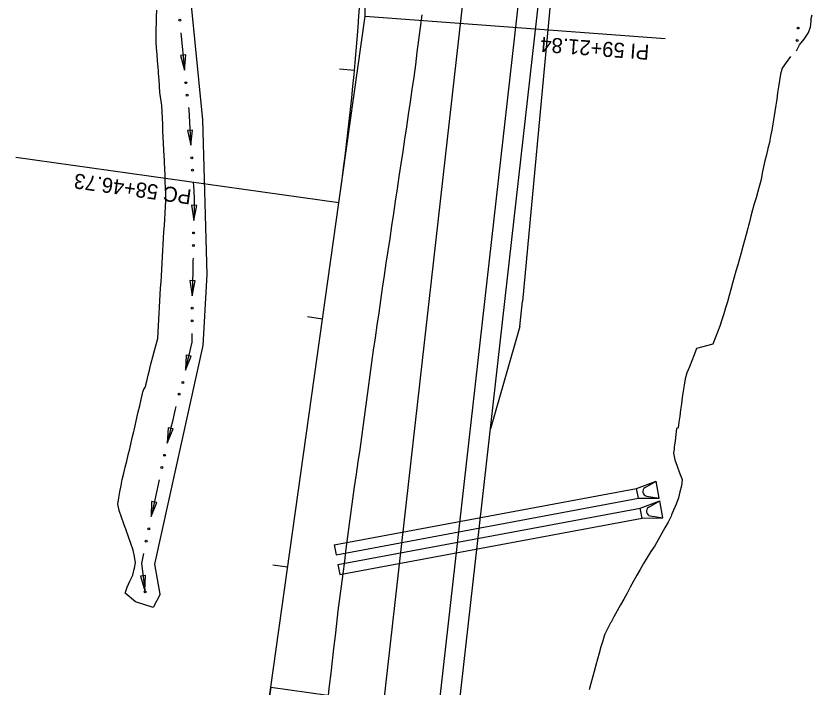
# Model space of a CAD drawing. Extents: x 1304554 to 1314558, y 2088110 to 2090513.
# Drawn here: x 1313857.1 to 1314174.4, y 2088772.7 to 2089040.4 of the extents above; entities that cross this region are included whole.
import ezdxf

# ---------------------------------------------------------------- set-up
doc = ezdxf.new("R2010")
doc.units = 0
for name, color, linetype in [('R_Drainage', 7, 'Continuous'), ('R_Horz Alg', 7, 'Continuous'), ('R_Horz Alg Annot', 7, 'Continuous'), ('R_Horz Alg Stationing', 7, 'Continuous'), ('R_Proposed Const Limits', 7, 'Continuous'), ('R_Proposed Road', 7, 'Continuous'), ('R_Shld_GR', 7, 'Continuous'), ('R_Shoulder', 7, 'Continuous'), ('R_Special Ditch', 7, 'Continuous')]:
    doc.layers.add(name, color=color, linetype=linetype)

msp = doc.modelspace()

# ---------------------------------------------------------------- linework, layer by layer
at = {"layer": 'R_Drainage'}
for p, q in [((1313924.75, 2089024.83), (1313922.64, 2089024.62)), ((1313922.64, 2089024.62), (1313924.29, 2089018.75)), ((1313924.29, 2089018.75), (1313924.75, 2089024.83)), ((1313927.5, 2088994.89), (1313925.39, 2088994.76)), ((1313925.39, 2088994.76), (1313926.8, 2088988.83)), ((1313926.8, 2088988.83), (1313927.5, 2088994.89)), ((1313929.19, 2088964.81), (1313927.07, 2088964.86)), ((1313927.07, 2088964.86), (1313927.98, 2088958.84)), ((1313927.98, 2088958.84), (1313929.19, 2088964.81)), ((1313928.54, 2088934.79), (1313926.43, 2088934.82)), ((1313926.43, 2088934.82), (1313927.38, 2088928.81)), ((1313927.38, 2088928.81), (1313928.54, 2088934.79)), ((1313924.87, 2088905.14), (1313924.61, 2088899.05)), ((1313924.61, 2088899.05), (1313926.94, 2088904.68)), ((1313926.94, 2088904.68), (1313924.87, 2088905.14)), ((1313917.72, 2088876.11), (1313917.4, 2088870.02)), ((1313917.4, 2088870.02), (1313919.78, 2088875.63)), ((1313919.78, 2088875.63), (1313917.72, 2088876.11)), ((1314104.47, 2088851.9), (1314112.23, 2088854.88)), ((1314107.82, 2088852.24), (1314112.23, 2088854.88)), ((1314113.51, 2088847.99), (1314112.23, 2088854.88)), ((1313983.92, 2088829.42), (1314104.47, 2088851.9)), ((1314105.2, 2088847.97), (1314104.47, 2088851.9)), ((1313911.17, 2088846.77), (1313910.97, 2088840.68)), ((1313913.24, 2088846.33), (1313911.17, 2088846.77)), ((1313984.65, 2088825.49), (1314105.2, 2088847.97)), ((1314105.2, 2088847.97), (1314113.51, 2088847.99)), ((1314105.94, 2088844.04), (1314113.69, 2088847.01)), ((1314108.46, 2088848.86), (1314113.51, 2088847.99)), ((1314109.29, 2088844.38), (1314113.69, 2088847.01)), ((1314114.98, 2088840.13), (1314113.69, 2088847.01)), ((1313910.97, 2088840.68), (1313913.24, 2088846.33)), ((1313985.38, 2088821.56), (1314105.94, 2088844.04)), ((1314106.67, 2088840.11), (1314105.94, 2088844.04)), ((1313986.12, 2088817.63), (1314106.67, 2088840.11)), ((1314106.67, 2088840.11), (1314114.98, 2088840.13)), ((1314109.92, 2088841), (1314114.98, 2088840.13)), ((1313983.92, 2088829.42), (1313984.65, 2088825.49)), ((1313985.38, 2088821.56), (1313986.12, 2088817.63)), ((1313908.77, 2088817.2), (1313906.67, 2088816.94)), ((1313906.67, 2088816.94), (1313908.44, 2088811.11)), ((1313908.44, 2088811.11), (1313908.77, 2088817.2))]:
    msp.add_line(p, q, dxfattribs=at)
for points in [[(1313922.82, 2089033.68), (1313924.29, 2089018.75)], [(1313925.86, 2089003.84), (1313925.86, 2089003.8)], [(1313925.86, 2089003.8), (1313925.98, 2089003.04), (1313926.12, 2089000.61), (1313926.26, 2088998.07), (1313926.41, 2088995.54), (1313926.55, 2088993.01), (1313926.7, 2088990.47), (1313926.8, 2088988.83)], [(1313927.71, 2088973.86), (1313927.71, 2088973.82)], [(1313927.71, 2088973.82), (1313927.78, 2088972.73), (1313927.94, 2088970.2), (1313928.1, 2088967.71), (1313928.14, 2088965.28), (1313928.08, 2088962.81), (1313928.02, 2088960.3), (1313927.98, 2088958.84)], [(1313927.66, 2088943.8), (1313927.63, 2088942.72), (1313927.58, 2088940.21), (1313927.54, 2088937.7), (1313927.49, 2088935.19), (1313927.45, 2088932.67), (1313927.41, 2088930.16), (1313927.38, 2088928.81)], [(1313927.66, 2088943.84), (1313927.66, 2088943.8)], [(1313927.17, 2088913.77), (1313927.15, 2088912.57), (1313927.13, 2088910.27), (1313926.61, 2088908.03), (1313926.06, 2088905.57), (1313925.51, 2088903.11), (1313924.96, 2088900.65), (1313924.61, 2088899.05)], [(1313920.84, 2088884.62), (1313920.59, 2088883.57), (1313920, 2088881.12), (1313919.41, 2088878.67), (1313918.83, 2088876.21), (1313918.26, 2088873.76), (1313918.14, 2088873.26), (1313917.69, 2088871.3), (1313917.4, 2088870.02)], [(1313920.85, 2088884.66), (1313920.84, 2088884.62)], [(1313914.12, 2088855.35), (1313913.84, 2088854.1), (1313913.31, 2088851.64), (1313912.78, 2088849.18), (1313912.25, 2088846.72), (1313911.73, 2088844.26), (1313911.21, 2088841.8), (1313910.97, 2088840.68)], [(1313914.12, 2088855.38), (1313914.12, 2088855.35)], [(1313907.94, 2088825.95), (1313907.13, 2088821.93), (1313908.39, 2088811.52)], [(1313907.95, 2088825.99), (1313907.94, 2088825.95)]]:
    msp.add_lwpolyline(points, dxfattribs=at)
for centre in [(1313922.36, 2089038.68), (1313924.81, 2089013.77), (1313925.3, 2089008.79), (1313927.13, 2088983.84), (1313927.44, 2088978.84), (1313927.9, 2088953.83), (1313927.79, 2088948.82), (1313927.34, 2088923.8), (1313927.27, 2088918.79), (1313923.6, 2088894.15), (1313922.07, 2088889.49), (1313916.33, 2088865.13), (1313915.23, 2088860.24), (1313909.98, 2088835.77), (1313908.98, 2088830.87), (1313908.55, 2088810.62), (1313908.55, 2088810.62)]:
    msp.add_circle(centre, 0.375, dxfattribs=at)
for centre in [(1314108.77, 2088850.67), (1314110.24, 2088842.81)]:
    msp.add_arc(centre, 1.83, 120.881, 260.2438, dxfattribs=at)
at = {"layer": 'R_Horz Alg'}
msp.add_line((1313958.64, 2088772.67), (1313985.8, 2088965.89), dxfattribs=at)
msp.add_line((1313958.64, 2088772.67), (1313985.8, 2088965.89), dxfattribs=at)
for centre, start, end in [((1312851.03, 2089125.37), 352, 359.5), ((1312851.03, 2089125.37), 352, 359.5), ((1315093.4, 2088613.19), 172, 187), ((1315093.4, 2088613.19), 172, 187)]:
    msp.add_arc(centre, 1145.92, start, end, dxfattribs=at)
at = {"layer": 'R_Horz Alg Annot'}
for points in [[(1313985.8, 2088965.89), (1313996.25, 2089040.27), (1313996.9, 2089115.37)], [(1313996.25, 2089040.27), (1314115.92, 2089031.38)], [(1313985.8, 2088965.89), (1313857.06, 2088983.99)], [(1313956.03, 2088473.54), (1313937.64, 2088623.28), (1313958.64, 2088772.67)], [(1313958.64, 2088772.67), (1314087.38, 2088754.58)]]:
    msp.add_lwpolyline(points, dxfattribs=at)
at = {"layer": 'R_Horz Alg Stationing'}
for points in [[(1313986.01, 2089019.36), (1313991.98, 2089018.8)], [(1313973.35, 2088920.45), (1313979.29, 2088919.62)], [(1313959.43, 2088821.43), (1313965.38, 2088820.59)]]:
    msp.add_lwpolyline(points, dxfattribs=at)
at = {"layer": 'R_Proposed Const Limits'}
for points in [[(1313914.54, 2088809.73), (1313912.39, 2088821.75), (1313931.7, 2088908.87), (1313933.34, 2088937.28), (1313931.57, 2088998.96), (1313916.24, 2089153.35)], [(1313915.23, 2089004.69), (1313914.49, 2089009.8), (1313914.29, 2089012.34), (1313914.1, 2089014.88), (1313913.91, 2089017.42), (1313913.87, 2089018.02), (1313913.84, 2089018.37), (1313913.72, 2089019.95), (1313913.53, 2089022.49), (1313913.33, 2089025.03), (1313913.12, 2089027.57), (1313912.92, 2089030.11), (1313912.95, 2089032.62), (1313913.01, 2089035.13), (1313913.08, 2089037.64), (1313913.14, 2089040.15), (1313913.18, 2089042.66)], [(1313981.46, 2088768.27), (1313982.06, 2088773.24), (1313982.66, 2088778.2), (1313983.25, 2088783.17), (1313983.85, 2088788.13), (1313984.43, 2088793.1), (1313985, 2088798.06), (1313985.57, 2088803.03), (1313986.15, 2088808), (1313986.81, 2088812.95), (1313987.46, 2088817.91), (1313988.11, 2088822.87), (1313988.75, 2088827.83), (1313989.4, 2088832.79), (1313990.04, 2088837.75), (1313990.71, 2088842.7), (1313991.38, 2088847.66), (1313992.08, 2088852.61), (1313992.8, 2088857.56), (1313993.52, 2088862.51), (1313994.24, 2088867.46), (1313994.97, 2088872.41), (1313995.66, 2088877.37), (1313996.34, 2088882.32), (1313996.98, 2088887.28), (1313997.62, 2088892.24), (1313998.27, 2088897.2), (1313998.96, 2088902.15), (1313999.66, 2088907.11), (1314000.37, 2088912.06), (1314001.08, 2088917.01), (1314001.79, 2088921.96), (1314002.5, 2088926.91), (1314003.22, 2088931.86), (1314003.95, 2088936.81), (1314004.67, 2088941.76), (1314005.43, 2088946.71), (1314006.18, 2088951.66), (1314006.91, 2088956.61), (1314007.65, 2088961.56), (1314008.38, 2088966.5), (1314009.13, 2088971.45), (1314009.87, 2088976.4), (1314010.63, 2088981.35), (1314011.39, 2088986.29), (1314012.12, 2088991.24), (1314012.84, 2088996.19), (1314013.57, 2089001.14), (1314014.3, 2089006.09), (1314015.04, 2089011.04), (1314015.77, 2089015.99), (1314016.42, 2089020.95), (1314017.06, 2089025.91), (1314017.73, 2089030.86), (1314018.38, 2089035.82), (1314019.01, 2089040.78)], [(1314168.16, 2089026.47), (1314169.41, 2089028.84), (1314171.31, 2089031.14), (1314172.82, 2089033.49), (1314173.83, 2089035.89), (1314174.04, 2089038.38), (1314174.12, 2089039.32), (1314174.42, 2089040.86)], [(1314165.83, 2089024.21), (1314164.13, 2089021.89), (1314162.45, 2089019.56), (1314161.86, 2089017.12), (1314161.45, 2089014.65), (1314161.04, 2089012.18), (1314160.65, 2089009.7), (1314160.31, 2089007.23), (1314159.96, 2089004.75), (1314159.61, 2089002.27), (1314159.2, 2088999.8), (1314158.78, 2088997.34), (1314158.35, 2088994.87), (1314157.91, 2088992.4), (1314157.63, 2088990.86), (1314157.55, 2088990.52), (1314157.41, 2088989.94), (1314156.8, 2088987.5), (1314156.2, 2088985.05), (1314155.61, 2088982.6), (1314155.03, 2088980.15), (1314154.54, 2088977.69), (1314154.07, 2088975.22), (1314153.45, 2088972.78), (1314152.76, 2088970.34), (1314152.08, 2088967.9), (1314151.39, 2088965.46), (1314150.7, 2088963.02), (1314150.06, 2088960.58), (1314149.43, 2088958.14), (1314149.08, 2088956.74), (1314148.8, 2088955.69), (1314148.14, 2088953.25), (1314147.47, 2088950.81), (1314146.8, 2088948.37), (1314146.13, 2088945.93), (1314145.45, 2088943.49), (1314144.77, 2088941.05), (1314144.09, 2088938.61), (1314143.4, 2088936.17), (1314142.72, 2088933.74), (1314142.03, 2088931.3), (1314141.34, 2088928.86), (1314140.65, 2088926.42), (1314139.95, 2088923.98), (1314139.24, 2088921.55), (1314138.47, 2088919.12), (1314137.69, 2088916.69), (1314136.78, 2088914.28), (1314135.8, 2088911.87), (1314134.82, 2088909.47), (1314128.38, 2088907.68), (1314127.42, 2088905.27), (1314126.46, 2088902.86), (1314125.5, 2088900.46), (1314124.54, 2088898.05), (1314123.87, 2088895.61), (1314123.37, 2088893.15), (1314123, 2088890.67), (1314122.66, 2088888.2), (1314122.32, 2088885.72), (1314121.98, 2088883.24), (1314121.64, 2088880.77), (1314121.29, 2088878.29), (1314120.98, 2088876.05), (1314120.39, 2088875.87), (1314120.09, 2088873.39), (1314119.79, 2088870.91), (1314119.49, 2088868.43), (1314119.39, 2088867.66), (1314119.22, 2088865.94), (1314119.67, 2088863.38), (1314120.65, 2088860.75), (1314121.63, 2088858.12), (1314122.61, 2088855.5), (1314122.36, 2088853.01), (1314121.75, 2088850.56), (1314121.18, 2088848.11), (1314120.21, 2088845.7), (1314119.23, 2088843.3), (1314118.43, 2088841.38), (1314118.23, 2088840.9), (1314117.08, 2088838.51), (1314115.71, 2088836.15), (1314114.38, 2088833.78), (1314113.05, 2088831.42), (1314111.68, 2088829.06), (1314110.19, 2088826.71), (1314108.7, 2088824.36), (1314107.21, 2088822.01), (1314105.9, 2088819.64), (1314104.59, 2088817.28), (1314103.27, 2088814.91), (1314101.96, 2088812.54), (1314100.65, 2088810.17), (1314099.35, 2088807.8), (1314098.04, 2088805.44), (1314096.73, 2088803.07), (1314095.43, 2088800.7), (1314094.29, 2088798.61), (1314094.13, 2088798.33), (1314092.83, 2088795.96), (1314091.65, 2088793.58), (1314090.95, 2088791.14), (1314090.27, 2088788.7), (1314089.6, 2088786.26), (1314088.93, 2088783.82), (1314088.26, 2088781.38), (1314087.58, 2088778.94), (1314086.89, 2088776.5), (1314086.21, 2088774.06), (1314085.54, 2088771.62)], [(1313900.65, 2088810.1), (1313901.39, 2088812.53), (1313902.53, 2088814.92), (1313903.66, 2088817.3), (1313904.25, 2088819.75), (1313904.32, 2088820.05), (1313904.79, 2088822.21), (1313904.39, 2088824.77), (1313903.85, 2088827.35), (1313902.88, 2088829.97), (1313901.95, 2088832.59), (1313901.02, 2088835.21), (1313900.09, 2088837.83), (1313899.17, 2088840.45), (1313898.25, 2088843.07), (1313897.62, 2088845.66), (1313898.06, 2088848.13), (1313898.5, 2088850.59), (1313898.95, 2088853.06), (1313899.41, 2088855.52), (1313900.02, 2088857.97), (1313900.63, 2088860.42), (1313901.24, 2088862.86), (1313901.86, 2088865.31), (1313902.47, 2088867.76), (1313903.01, 2088870.21), (1313903.57, 2088872.66), (1313904.01, 2088874.63), (1313904.13, 2088875.12), (1313904.69, 2088877.57), (1313905.26, 2088880.02), (1313905.83, 2088882.47), (1313906.41, 2088884.92), (1313906.99, 2088887.37), (1313907.58, 2088889.82), (1313907.7, 2088890.31), (1313907.99, 2088891.52), (1313908.64, 2088892.22), (1313909.18, 2088894.67), (1313909.79, 2088897.12), (1313910.41, 2088899.57), (1313910.47, 2088899.8), (1313911.03, 2088902.01), (1313911.66, 2088904.46), (1313912.29, 2088906.9), (1313912.93, 2088909.35), (1313913.58, 2088911.79), (1313913.72, 2088914.29), (1313913.87, 2088916.79), (1313914.03, 2088919.29), (1313914.17, 2088921.79), (1313914.31, 2088924.28), (1313914.45, 2088926.78), (1313914.6, 2088929.28), (1313914.75, 2088931.78), (1313914.9, 2088934.28), (1313915.04, 2088936.78), (1313915.2, 2088939.28), (1313915.36, 2088941.78), (1313915.51, 2088944.28), (1313915.65, 2088946.78), (1313915.79, 2088949.28), (1313915.94, 2088951.78), (1313916.08, 2088954.28), (1313916.23, 2088956.78), (1313916.37, 2088959.27), (1313916.52, 2088961.77), (1313916.67, 2088964.27), (1313916.82, 2088966.77), (1313916.81, 2088969.29), (1313916.71, 2088971.82), (1313916.6, 2088974.34), (1313916.5, 2088976.87), (1313916.4, 2088979.4), (1313916.27, 2088981.93), (1313916.22, 2088983.01), (1313916.15, 2088984.46), (1313916.04, 2088986.99), (1313915.92, 2088989.52), (1313915.81, 2088992.04), (1313915.68, 2088994.57), (1313915.56, 2088997.1), (1313915.45, 2088999.63), (1313915.34, 2089002.16), (1313915.23, 2089004.69)], [(1313914.54, 2088809.73), (1313911.8, 2088804.4), (1313904.7, 2088806.72), (1313900.65, 2088810.1)]]:
    msp.add_lwpolyline(points, dxfattribs=at)
at = {"layer": 'R_Proposed Road'}
for p, q in [((1313991.22, 2088655.7), (1314042.63, 2089111.32)), ((1314013.09, 2088653.23), (1314064.49, 2089108.85))]:
    msp.add_line(p, q, dxfattribs=at)
at = {"layer": 'R_Shld_GR'}
for p, q in [((1314075.17, 2089100.87), (1314059.02, 2088926.55)), ((1314057.89, 2088916.58), (1314059.02, 2088926.55)), ((1314057.89, 2088916.58), (1314046.23, 2088875.63))]:
    msp.add_line(p, q, dxfattribs=at)
at = {"layer": 'R_Shoulder'}
msp.add_line((1314021.03, 2088652.34), (1314072.44, 2089107.95), dxfattribs=at)
at = {"layer": 'R_Special Ditch'}
for centre in [(1314168.88, 2089035.57), (1314168.88, 2089035.57), (1314168.52, 2089030.57), (1314168.52, 2089030.57)]:
    msp.add_circle(centre, 0.375, dxfattribs=at)

# ---------------------------------------------------------------- texts
at = {"layer": 'R_Horz Alg Annot'}
for s, rotation, p in [('PI 59+21.84', 175.75, (1314109.71, 2089028.83)), ('PC 58+46.73', 172, (1313927.32, 2088971.08))]:
    msp.add_text(s, height=6, rotation=rotation, dxfattribs=at).set_placement(p)

doc.saveas('drawing.dxf')
